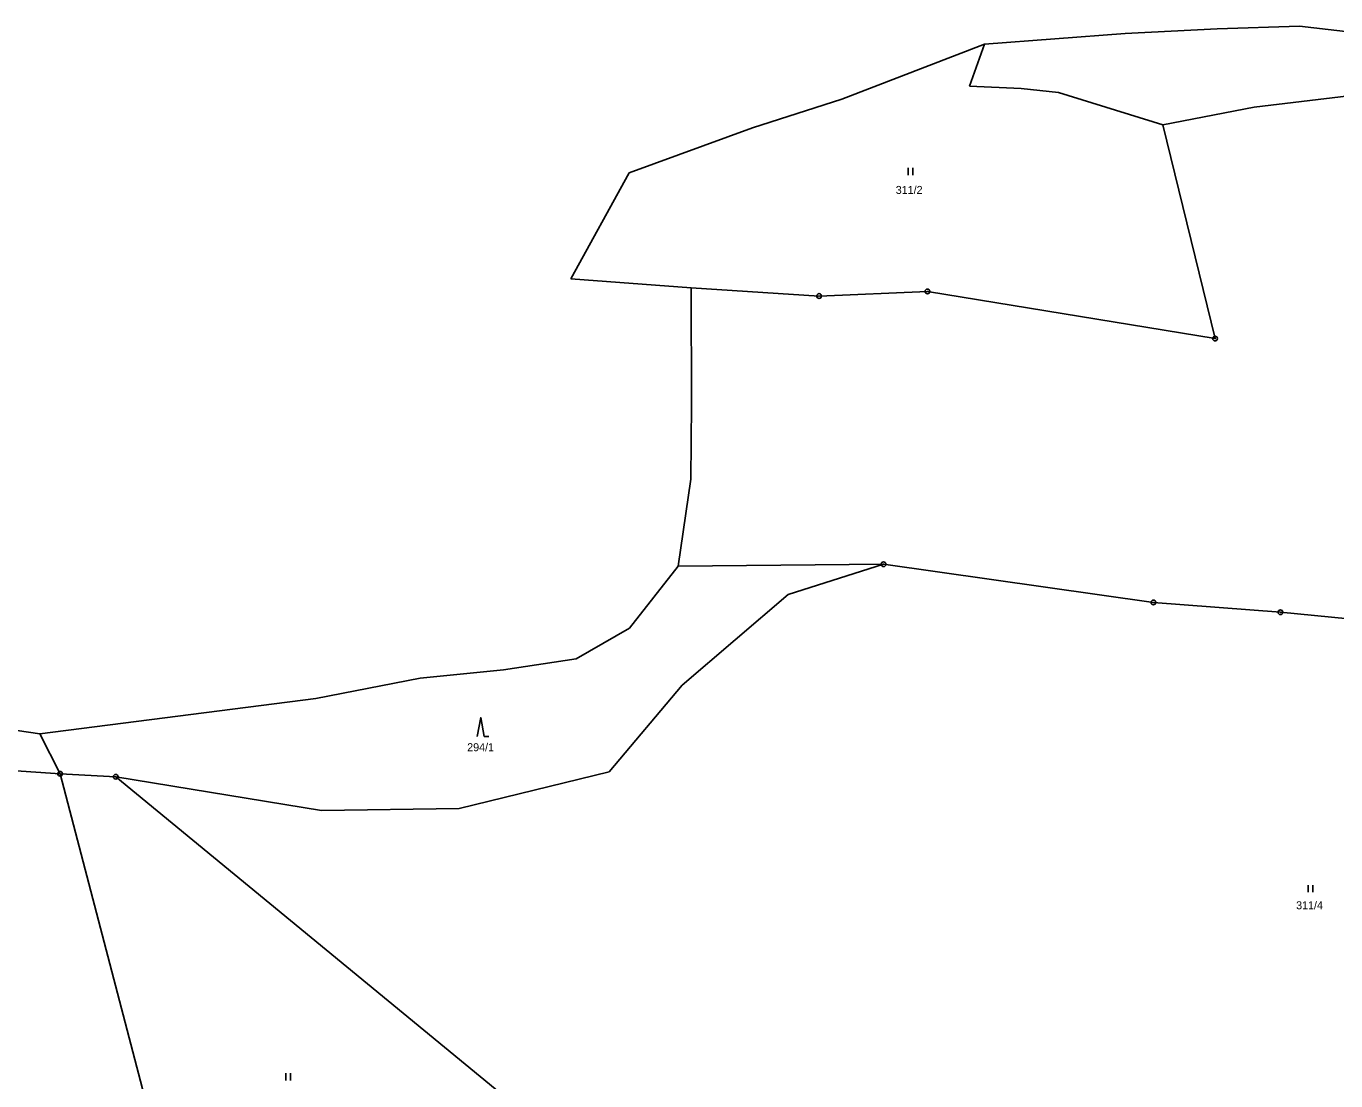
# Model space of a CAD drawing. Extents: x -754970 to -752637, y -970569 to -968179.
# Drawn here: x -754191 to -753912.9, y -968596.7 to -968372.6 of the extents above; entities that cross this region are included whole.
import ezdxf
from ezdxf.enums import TextEntityAlignment as Align

# ---------------------------------------------------------------- set-up
doc = ezdxf.new("R2010")
doc.units = 0
doc.header["$LTSCALE"] = 0.68
for name, color, linetype, lineweight in [('1', 7, 'Continuous', 25), ('3', 7, 'Continuous', 25), ('8', 7, 'Continuous', 25)]:
    doc.layers.add(name, color=color, linetype=linetype, lineweight=lineweight)
doc.layers.add('2', color=7, linetype='Continuous')

msp = doc.modelspace()

# ---------------------------------------------------------------- linework, layer by layer
at = {"layer": '1'}
for p, q in [((-753938.04, -968373.17), (-753920.58, -968372.64)), ((-753920.58, -968372.64), (-753894.83, -968375.66)), ((-753987.44, -968376.47), (-753957.6, -968374.19)), ((-753957.6, -968374.19), (-753938.04, -968373.17)), ((-754017.76, -968388.17), (-753987.44, -968376.47)), ((-753990.69, -968385.35), (-753987.44, -968376.47)), ((-753990.69, -968385.35), (-753979.71, -968385.86)), ((-753971.76, -968386.71), (-753979.71, -968385.86)), ((-753949.59, -968393.57), (-753971.76, -968386.71)), ((-754036.77, -968394.25), (-754017.76, -968388.17)), ((-753930.19, -968389.85), (-753910.07, -968387.44)), ((-753949.59, -968393.57), (-753930.19, -968389.85)), ((-754062.94, -968403.77), (-754036.77, -968394.25)), ((-753938.51, -968439), (-753949.59, -968393.57)), ((-754075.3, -968426.3), (-754062.94, -968403.77)), ((-754049.75, -968428.2), (-754075.3, -968426.3)), ((-754049.75, -968428.2), (-754022.59, -968429.96)), ((-754049.71, -968452.99), (-754049.75, -968428.2)), ((-754022.59, -968429.96), (-753999.58, -968429)), ((-753999.58, -968429), (-753938.51, -968439)), ((-754049.84, -968468.9), (-754049.71, -968452.99)), ((-754052.54, -968487.36), (-754049.84, -968468.9)), ((-754008.9, -968486.93), (-754052.54, -968487.36)), ((-754029.18, -968493.35), (-754008.9, -968486.93)), ((-754008.9, -968486.93), (-753951.61, -968495.06)), ((-754062.83, -968500.53), (-754052.54, -968487.36)), ((-754051.7, -968512.65), (-754029.18, -968493.35)), ((-753951.61, -968495.06), (-753924.64, -968497.14)), ((-753924.64, -968497.14), (-753890.6, -968500.44)), ((-754074.17, -968507.03), (-754062.83, -968500.53)), ((-754089.61, -968509.39), (-754074.17, -968507.03)), ((-754129.43, -968515.49), (-754107.28, -968511.12)), ((-754107.28, -968511.12), (-754089.61, -968509.39)), ((-754067.2, -968531.05), (-754051.7, -968512.65)), ((-754129.43, -968515.49), (-754188.09, -968522.93)), ((-754210.71, -968519.66), (-754188.09, -968522.93)), ((-754183.76, -968531.43), (-754188.09, -968522.93)), ((-754202.9, -968530.13), (-754183.76, -968531.43)), ((-754183.76, -968531.43), (-754171.96, -968532.09)), ((-754183.76, -968531.43), (-754149.44, -968662.92)), ((-754098.99, -968538.79), (-754067.2, -968531.05)), ((-754171.96, -968532.09), (-754128.28, -968539.25)), ((-754171.96, -968532.09), (-754073.1, -968613.4)), ((-754128.28, -968539.25), (-754098.99, -968538.79))]:
    msp.add_line(p, q, dxfattribs=at)
at = {"layer": '3'}
for p, q in [((-754003.691, -968404.26), (-754003.691, -968402.76)), ((-754002.69, -968404.26), (-754002.69, -968402.76)), ((-754093.69, -968523.5), (-754092.694, -968523.5)), ((-753918.741, -968556.58), (-753918.741, -968555.08)), ((-753917.74, -968556.58), (-753917.74, -968555.08)), ((-754135.811, -968596.58), (-754135.811, -968595.08)), ((-754134.81, -968596.58), (-754134.81, -968595.08))]:
    msp.add_line(p, q, dxfattribs=at)
msp.add_lwpolyline([(-754093.69, -968523.5), (-754094.44, -968519.5), (-754095.19, -968523.5)], dxfattribs=at)
at = {"layer": '8'}
for centre, radius in [((-753999.58, -968428.9999), 0.5), ((-754022.59, -968429.9599), 0.5), ((-754022.59, -968429.9599), 0.0303), ((-753999.58, -968428.9999), 0.0303), ((-753938.51, -968438.9999), 0.5), ((-753938.51, -968438.9999), 0.0303), ((-754008.9, -968486.9299), 0.5), ((-754008.9, -968486.9299), 0.0303), ((-753951.61, -968495.0599), 0.5), ((-753951.61, -968495.0599), 0.0303), ((-753924.64, -968497.1399), 0.5), ((-753924.64, -968497.1399), 0.0303), ((-754183.76, -968531.4299), 0.5), ((-754183.76, -968531.4299), 0.0303), ((-754171.96, -968532.0899), 0.5), ((-754171.96, -968532.0899), 0.0303)]:
    msp.add_circle(centre, radius, dxfattribs=at)

# ---------------------------------------------------------------- texts
at = {"layer": '2'}
for s, p in [('311/2', (-754003.47, -968408.275)), ('294/1', (-754094.47, -968526.655)), ('311/4', (-753918.45, -968560.235))]:
    msp.add_text(s, height=1.7, dxfattribs=at).set_placement(p, align=Align.CENTER)

doc.saveas('drawing.dxf')
